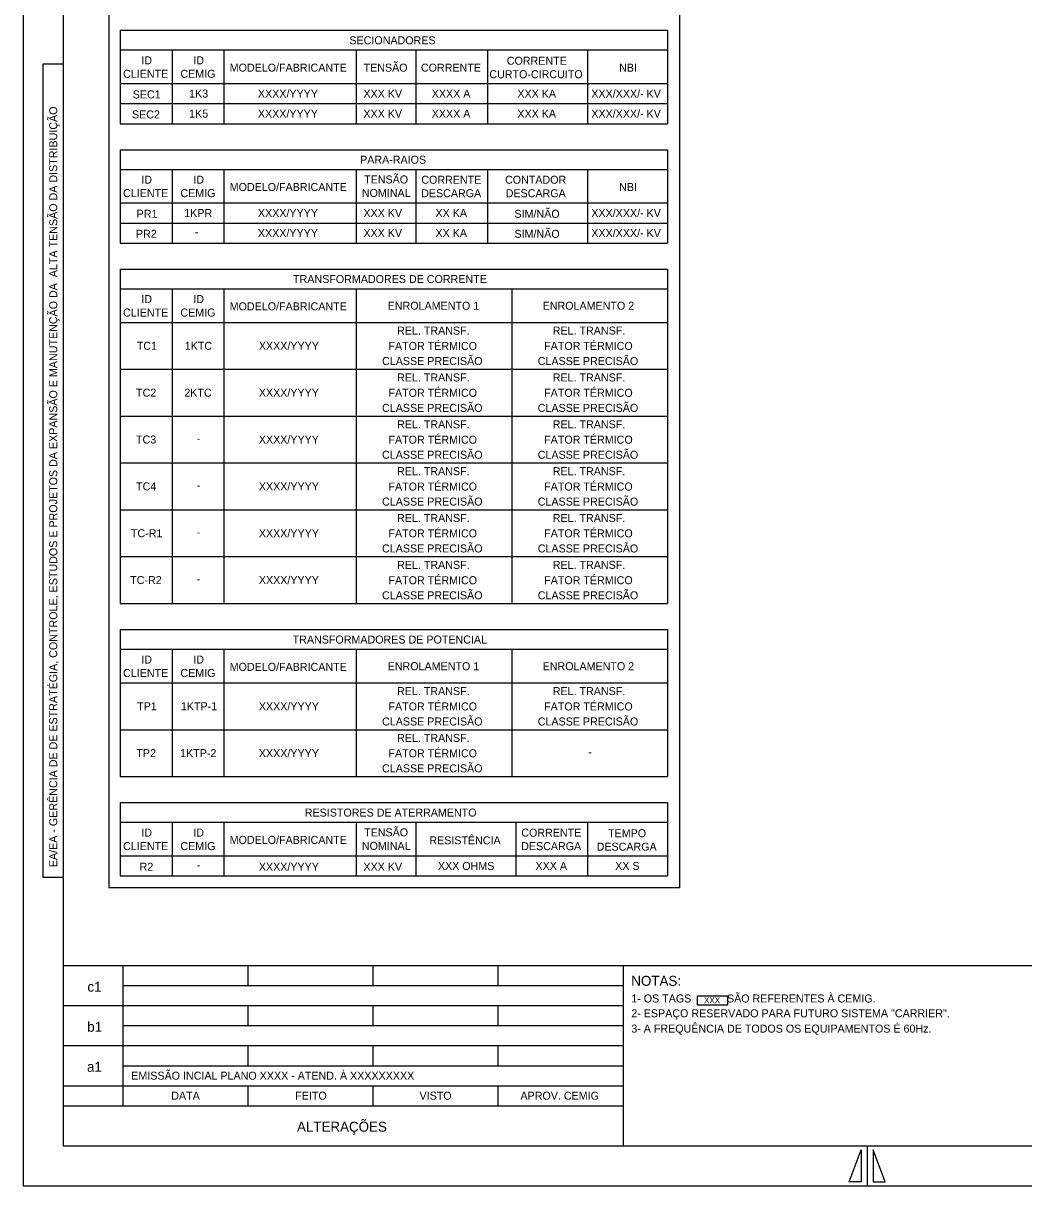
# Model space of a CAD drawing. Extents: x 563 to 1404, y 358 to 952.
# Drawn here: x 562.6 to 812.7, y 358 to 648.4 of the extents above; entities that cross this region are included whole.
import ezdxf

# ---------------------------------------------------------------- set-up
doc = ezdxf.new("R2010")
doc.units = 0
doc.layers.add('New Level (0)', color=7, linetype='Continuous')

# ---------------------------------------------------------------- blocks, each defined once
blk = doc.blocks.new('POINT_DISPLAY')
blk.add_line((0, 0), (0, 0))

msp = doc.modelspace()

# ---------------------------------------------------------------- linework, layer by layer
at = {"layer": 'New Level (0)'}
for p, q in [((562.58, 951.96), (562.58, 357.96)), ((562.58, 951.96), (562.58, 357.96)), ((572.58, 941.96), (572.58, 367.96)), ((572.58, 941.96), (572.58, 367.96)), ((583.96, 679.5), (583.96, 432.32)), ((726.65, 679.5), (726.65, 432.37)), ((586.81, 646.67), (586.81, 623.34)), ((586.81, 646.67), (723.65, 646.67)), ((723.65, 646.67), (723.65, 623.34)), ((723.65, 641.67), (586.81, 641.67)), ((599.81, 641.67), (599.81, 623.34)), ((612.81, 623.34), (612.81, 641.67)), ((645.81, 641.67), (645.81, 623.34)), ((660.72, 641.67), (660.72, 623.34)), ((678.66, 641.67), (678.66, 623.34)), ((703.66, 641.67), (703.66, 623.34)), ((567.58, 638.29), (572.58, 638.29)), ((567.58, 434.97), (567.58, 638.29)), ((586.81, 633.34), (723.65, 633.34)), ((586.81, 628.34), (723.65, 628.34)), ((586.81, 623.34), (723.65, 623.34)), ((586.81, 616.84), (586.81, 593.52)), ((586.81, 616.84), (723.65, 616.84)), ((723.65, 616.84), (723.65, 593.52)), ((723.65, 611.84), (586.81, 611.84)), ((599.81, 611.84), (599.81, 593.52)), ((612.81, 593.52), (612.81, 611.84)), ((645.81, 611.84), (645.81, 593.52)), ((660.72, 611.84), (660.72, 593.52)), ((678.66, 611.84), (678.66, 593.52)), ((703.66, 611.84), (703.66, 593.52)), ((586.81, 603.52), (723.65, 603.52)), ((629.06, 603.52), (723.65, 603.52)), ((586.81, 598.52), (723.65, 598.52)), ((586.81, 593.52), (723.65, 593.52)), ((586.81, 587.02), (586.81, 503.44)), ((586.81, 587.02), (723.65, 587.02)), ((723.65, 587.02), (723.65, 503.44)), ((723.65, 582.02), (586.81, 582.02)), ((599.81, 582.02), (599.81, 503.44)), ((612.81, 503.44), (612.81, 582.02)), ((645.81, 582.02), (645.81, 503.44)), ((684.73, 582.02), (684.73, 503.44)), ((586.81, 573.69), (723.65, 573.69)), ((586.81, 561.98), (723.65, 561.98)), ((586.81, 550.27), (723.65, 550.27)), ((586.81, 538.57), (723.65, 538.57)), ((586.81, 526.86), (723.65, 526.86)), ((586.81, 515.15), (723.65, 515.15)), ((586.81, 503.44), (723.65, 503.44)), ((586.81, 503.44), (586.81, 503.44)), ((586.81, 503.44), (586.81, 503.44)), ((586.81, 496.94), (586.81, 460.2)), ((586.81, 496.94), (723.65, 496.94)), ((723.65, 496.94), (723.65, 460.2)), ((723.65, 491.94), (586.81, 491.94)), ((599.81, 491.94), (599.81, 460.2)), ((612.81, 460.2), (612.81, 491.94)), ((645.81, 491.94), (645.81, 460.2)), ((684.73, 491.94), (684.73, 460.2)), ((586.81, 483.61), (723.65, 483.61)), ((586.81, 471.91), (723.65, 471.91)), ((586.81, 460.2), (723.65, 460.2)), ((586.81, 453.7), (586.81, 435.37)), ((586.81, 453.7), (723.65, 453.7)), ((723.65, 453.7), (723.65, 435.37)), ((723.65, 448.7), (586.81, 448.7)), ((599.81, 448.7), (599.81, 435.37)), ((612.81, 435.37), (612.81, 448.7)), ((645.81, 448.7), (645.81, 435.37)), ((660.72, 448.7), (660.72, 435.37)), ((685.72, 448.7), (685.72, 435.37)), ((703.66, 448.7), (703.66, 435.37)), ((703.66, 448.7), (703.66, 435.37)), ((586.81, 440.37), (723.65, 440.37)), ((629.06, 440.37), (723.65, 440.37)), ((572.58, 434.97), (567.58, 434.97)), ((586.81, 435.37), (723.65, 435.37)), ((726.65, 432.37), (583.96, 432.37)), ((572.58, 412.96), (1393.58, 412.96)), ((587.58, 377.96), (587.58, 412.96)), ((618.83, 407.96), (618.83, 412.96)), ((650.08, 407.96), (650.08, 412.96)), ((681.33, 407.96), (681.33, 412.96)), ((712.58, 412.96), (712.58, 367.96)), ((587.58, 407.96), (712.58, 407.96)), ((572.58, 402.96), (712.58, 402.96)), ((618.83, 397.96), (618.83, 402.96)), ((650.08, 397.96), (650.08, 402.96)), ((681.33, 397.96), (681.33, 402.96)), ((587.58, 397.96), (712.58, 397.96)), ((572.58, 392.96), (712.58, 392.96)), ((618.83, 387.96), (618.83, 392.96)), ((650.08, 387.96), (650.08, 392.96)), ((681.33, 387.96), (681.33, 392.96)), ((587.58, 387.96), (712.58, 387.96)), ((572.58, 382.96), (712.58, 382.96)), ((618.83, 377.96), (618.83, 382.96)), ((650.08, 377.96), (650.08, 382.96)), ((681.33, 377.96), (681.33, 382.96)), ((572.58, 377.96), (712.58, 377.96)), ((572.58, 367.96), (1393.58, 367.96)), ((572.58, 367.96), (1393.58, 367.96)), ((769.08, 358.96), (772.08, 366.96)), ((772.08, 366.96), (772.08, 358.96)), ((773.58, 367.96), (773.58, 357.96)), ((775.08, 366.96), (775.08, 358.96)), ((778.08, 358.96), (775.08, 366.96)), ((562.58, 357.96), (1403.58, 357.96)), ((562.58, 357.96), (1403.58, 357.96)), ((772.08, 358.96), (769.08, 358.96)), ((775.08, 358.96), (778.08, 358.96))]:
    msp.add_line(p, q, dxfattribs=at)
msp.add_lwpolyline([(731.16, 405.44), (738.67, 405.44), (738.67, 403.1), (731.16, 403.1)], close=True, dxfattribs=at)

# ---------------------------------------------------------------- block references
for p in [(655.23, 573.69), (655.23, 483.61)]:
    msp.add_blockref('POINT_DISPLAY', p, dxfattribs=at)

# ---------------------------------------------------------------- texts
for s, height, p in [('SECIONADORES', 2, (644.11, 643.17)), ('ID', 2, (592.1, 638.17)), ('ID', 2, (605.1, 638.17)), ('CORRENTE', 2, (683.46, 638.07)), ('CLIENTE', 2, (587.54, 634.8)), ('CEMIG', 2, (601.87, 634.8)), ('MODELO/FABRICANTE', 2, (614.19, 636.34)), ('TENSÃO', 2, (647.65, 636.34)), ('CORRENTE', 2, (661.99, 636.34)), ('CURTO-CIRCUITO', 2, (679.1, 634.7)), ('NBI', 2, (711.56, 636.34)), ('SEC1', 2, (589.94, 629.65)), ('1K3', 2, (604.04, 629.86)), ('XXXX/YYYY', 2, (621.24, 629.84)), ('XXX KV', 2, (647.62, 629.84)), ('XXXX A', 2, (664.7, 629.84)), ('XXX KA', 2, (686.11, 629.84)), ('XXX/XXX/- KV', 2, (704.59, 629.84)), ('SEC2', 2, (589.76, 624.65)), ('1K5', 2, (604.04, 624.86)), ('XXXX/YYYY', 2, (621.24, 624.84)), ('XXX KV', 2, (647.62, 624.84)), ('XXXX A', 2, (664.7, 624.84)), ('XXX KA', 2, (686.11, 624.84)), ('XXX/XXX/- KV', 2, (704.59, 624.84)), ('PARA-RAIOS', 2, (646.79, 613.34)), ('ID', 2, (592.1, 608.34)), ('ID', 2, (605.1, 608.34)), ('TENSÃO ', 2, (647.79, 608.4)), ('CORRENTE', 2, (662.09, 608.33)), ('CONTADOR', 2, (683.02, 608.33)), ('MODELO/FABRICANTE', 2, (614.19, 606.52)), ('NBI', 2, (711.56, 606.52)), ('CLIENTE', 2, (587.54, 604.98)), ('CEMIG', 2, (601.87, 604.98)), ('NOMINAL', 2, (647.23, 605.03)), ('DESCARGA', 2, (662.05, 604.96)), ('DESCARGA', 2, (683.19, 604.96)), ('PR1', 2, (590.92, 599.82)), ('1KPR', 2, (602.83, 600.01)), ('XXXX/YYYY', 2, (621.24, 600.02)), ('XXX KV', 2, (647.62, 600.02)), ('XX KA', 2, (665.63, 600.02)), ('SIM/NÃO', 2, (685.38, 599.82)), ('XXX/XXX/- KV', 2, (704.59, 600.02)), ('PR2', 2, (590.74, 594.82)), ('-', 2, (605.47, 595.29)), ('XXXX/YYYY', 2, (621.24, 595.02)), ('XXX KV', 2, (647.62, 595.02)), ('XX KA', 2, (665.63, 595.02)), ('SIM/NÃO', 2, (685.38, 594.82)), ('XXX/XXX/- KV', 2, (704.59, 595.02)), ('TRANSFORMADORES DE CORRENTE', 2, (630.03, 583.52)), ('ID', 2, (592.1, 578.52)), ('ID', 2, (605.1, 578.52)), ('MODELO/FABRICANTE', 2, (614.19, 576.69)), ('ENROLAMENTO 1', 2, (653.68, 576.85)), ('ENROLAMENTO 2', 2, (692.42, 576.85)), ('CLIENTE', 2, (587.54, 575.15)), ('CEMIG', 2, (601.87, 575.15)), ('REL. TRANSF.', 2, (656.03, 570.64)), ('REL. TRANSF.', 2, (694.95, 570.64)), ('TC1', 2, (590.96, 566.83)), ('1KTC', 2, (602.95, 566.83)), ('XXXX/YYYY', 2, (621.48, 566.83)), ('FATOR TÉRMICO', 2, (653.88, 566.8)), ('FATOR TÉRMICO', 2, (692.8, 566.8)), ('CLASSE PRECISÃO', 2, (652.28, 563.03)), ('CLASSE PRECISÃO', 2, (691.2, 563.03)), ('REL. TRANSF.', 2, (656.03, 558.93)), ('REL. TRANSF.', 2, (694.95, 558.93)), ('TC2', 2, (590.78, 555.13)), ('2KTC', 2, (602.84, 555.13)), ('XXXX/YYYY', 2, (621.48, 555.13)), ('FATOR TÉRMICO', 2, (653.88, 555.09)), ('FATOR TÉRMICO', 2, (692.8, 555.09)), ('CLASSE PRECISÃO', 2, (652.28, 551.32)), ('CLASSE PRECISÃO', 2, (691.2, 551.32)), ('REL. TRANSF.', 2, (656.03, 547.22)), ('REL. TRANSF.', 2, (694.95, 547.22)), ('TC3', 2, (590.77, 543.42)), ('-', 2, (605.94, 543.7)), ('XXXX/YYYY', 2, (621.48, 543.42)), ('FATOR TÉRMICO', 2, (653.88, 543.38)), ('FATOR TÉRMICO', 2, (692.8, 543.38)), ('CLASSE PRECISÃO', 2, (652.28, 539.61)), ('CLASSE PRECISÃO', 2, (691.2, 539.61)), ('REL. TRANSF.', 2, (656.03, 535.51)), ('REL. TRANSF.', 2, (694.95, 535.51)), ('TC4', 2, (590.78, 531.71)), ('-', 2, (605.94, 531.99)), ('XXXX/YYYY', 2, (621.48, 531.71)), ('FATOR TÉRMICO', 2, (653.88, 531.67)), ('FATOR TÉRMICO', 2, (692.8, 531.67)), ('CLASSE PRECISÃO', 2, (652.28, 527.91)), ('CLASSE PRECISÃO', 2, (691.2, 527.91)), ('REL. TRANSF.', 2, (656.03, 523.81)), ('REL. TRANSF.', 2, (694.95, 523.81)), ('TC-R1', 2, (589.49, 520)), ('-', 2, (605.94, 520.28)), ('XXXX/YYYY', 2, (621.48, 520)), ('FATOR TÉRMICO', 2, (653.88, 519.97)), ('FATOR TÉRMICO', 2, (692.8, 519.97)), ('CLASSE PRECISÃO', 2, (652.28, 516.2)), ('CLASSE PRECISÃO', 2, (691.2, 516.2)), ('REL. TRANSF.', 2, (656.03, 512.1)), ('REL. TRANSF.', 2, (694.95, 512.1)), ('TC-R2', 2, (589.31, 508.3)), ('-', 2, (605.94, 508.57)), ('XXXX/YYYY', 2, (621.48, 508.3)), ('FATOR TÉRMICO', 2, (653.88, 508.26)), ('FATOR TÉRMICO', 2, (692.8, 508.26)), ('CLASSE PRECISÃO', 2, (652.28, 504.49)), ('CLASSE PRECISÃO', 2, (691.2, 504.49)), ('TRANSFORMADORES DE POTENCIAL', 2, (629.92, 493.44)), ('ID', 2, (592.1, 488.44)), ('ID', 2, (605.1, 488.44)), ('MODELO/FABRICANTE', 2, (614.19, 486.61)), ('ENROLAMENTO 1', 2, (653.68, 486.78)), ('ENROLAMENTO 2', 2, (692.42, 486.78)), ('CLIENTE', 2, (587.54, 485.07)), ('CEMIG', 2, (601.87, 485.07)), ('REL. TRANSF.', 2, (656.03, 480.56)), ('REL. TRANSF.', 2, (694.95, 480.56)), ('TP1', 2, (591.04, 476.76)), ('1KTP-1', 2, (601.99, 476.76)), ('XXXX/YYYY', 2, (621.48, 476.76)), ('FATOR TÉRMICO', 2, (653.88, 476.72)), ('FATOR TÉRMICO', 2, (692.8, 476.72)), ('CLASSE PRECISÃO', 2, (652.28, 472.96)), ('CLASSE PRECISÃO', 2, (691.2, 472.96)), ('REL. TRANSF.', 2, (656.03, 468.86)), ('TP2', 2, (590.86, 465.05)), ('1KTP-2', 2, (601.8, 465.05)), ('XXXX/YYYY', 2, (621.48, 465.05)), ('FATOR TÉRMICO', 2, (653.88, 465.02)), ('-', 2, (703.81, 465.33)), ('CLASSE PRECISÃO', 2, (652.28, 461.25)), ('RESISTORES DE ATERRAMENTO', 2, (632.96, 450.2)), ('TENSÃO ', 2, (647.79, 445.25)), ('ID', 2, (592.1, 445.2)), ('ID', 2, (605.1, 445.2)), ('MODELO/FABRICANTE', 2, (614.19, 443.37)), ('RESISTÊNCIA', 2, (664.09, 443.26)), ('CORRENTE', 2, (687.09, 445.18)), ('TEMPO', 2, (708.78, 445.05)), ('CLIENTE', 2, (587.54, 441.83)), ('CEMIG', 2, (601.87, 441.83)), ('NOMINAL', 2, (647.23, 441.88)), ('DESCARGA', 2, (687.05, 441.81)), ('DESCARGA', 2, (705.92, 441.69)), ('R2', 2, (591.67, 436.67)), ('XXXX/YYYY', 2, (621.48, 436.67)), ('XXX KV', 2, (647.62, 436.67)), ('XXX OHMS', 2, (666.24, 436.87)), ('XXX A', 2, (690.63, 436.87)), ('XX S', 2, (710.55, 436.87)), ('-', 2, (605.94, 437.15)), ('XXX', 1.5, (732.77, 403.54))]:
    msp.add_text(s, height=height).set_placement(p)
msp.add_text('EA/EA - GERÊNCIA DE DE ESTRATÉGIA, CONTROLE, ESTUDOS E PROJETOS DA EXPANSÃO E MANUTENÇÃO DA  ALTA TENSÃO DA DISTRIBUIÇÃO', height=2, rotation=90, dxfattribs=at).set_placement((571.08, 437.56))
for s, height, p in [('NOTAS:', 2.5, (714.58, 407.91)), ('c1', 2.5, (578.62, 406.44)), ('1- OS TAGS            SÃO REFERENTES À CEMIG.', 2, (714.58, 403.75)), ('2- ESPAÇO RESERVADO PARA FUTURO SISTEMA "CARRIER".', 2, (714.58, 400.05)), ('b1', 2.5, (578.57, 396.44)), ('3- A FREQUÊNCIA DE TODOS OS EQUIPAMENTOS É 60Hz.', 2, (714.58, 396.22)), ('a1', 2.5, (578.52, 386.44)), ('EMISSÃO INCIAL PLANO XXXX - ATEND. À XXXXXXXXX', 2, (589.58, 384.46)), ('DATA', 2, (599.58, 379.46)), ('FEITO', 2, (630.58, 379.46)), ('VISTO', 2, (661.64, 379.46)), ('APROV. CEMIG', 2, (686.88, 379.46)), ('ALTERAÇÕES', 2.5, (631.01, 371.46))]:
    msp.add_text(s, height=height, dxfattribs=at).set_placement(p)

doc.saveas('drawing.dxf')
